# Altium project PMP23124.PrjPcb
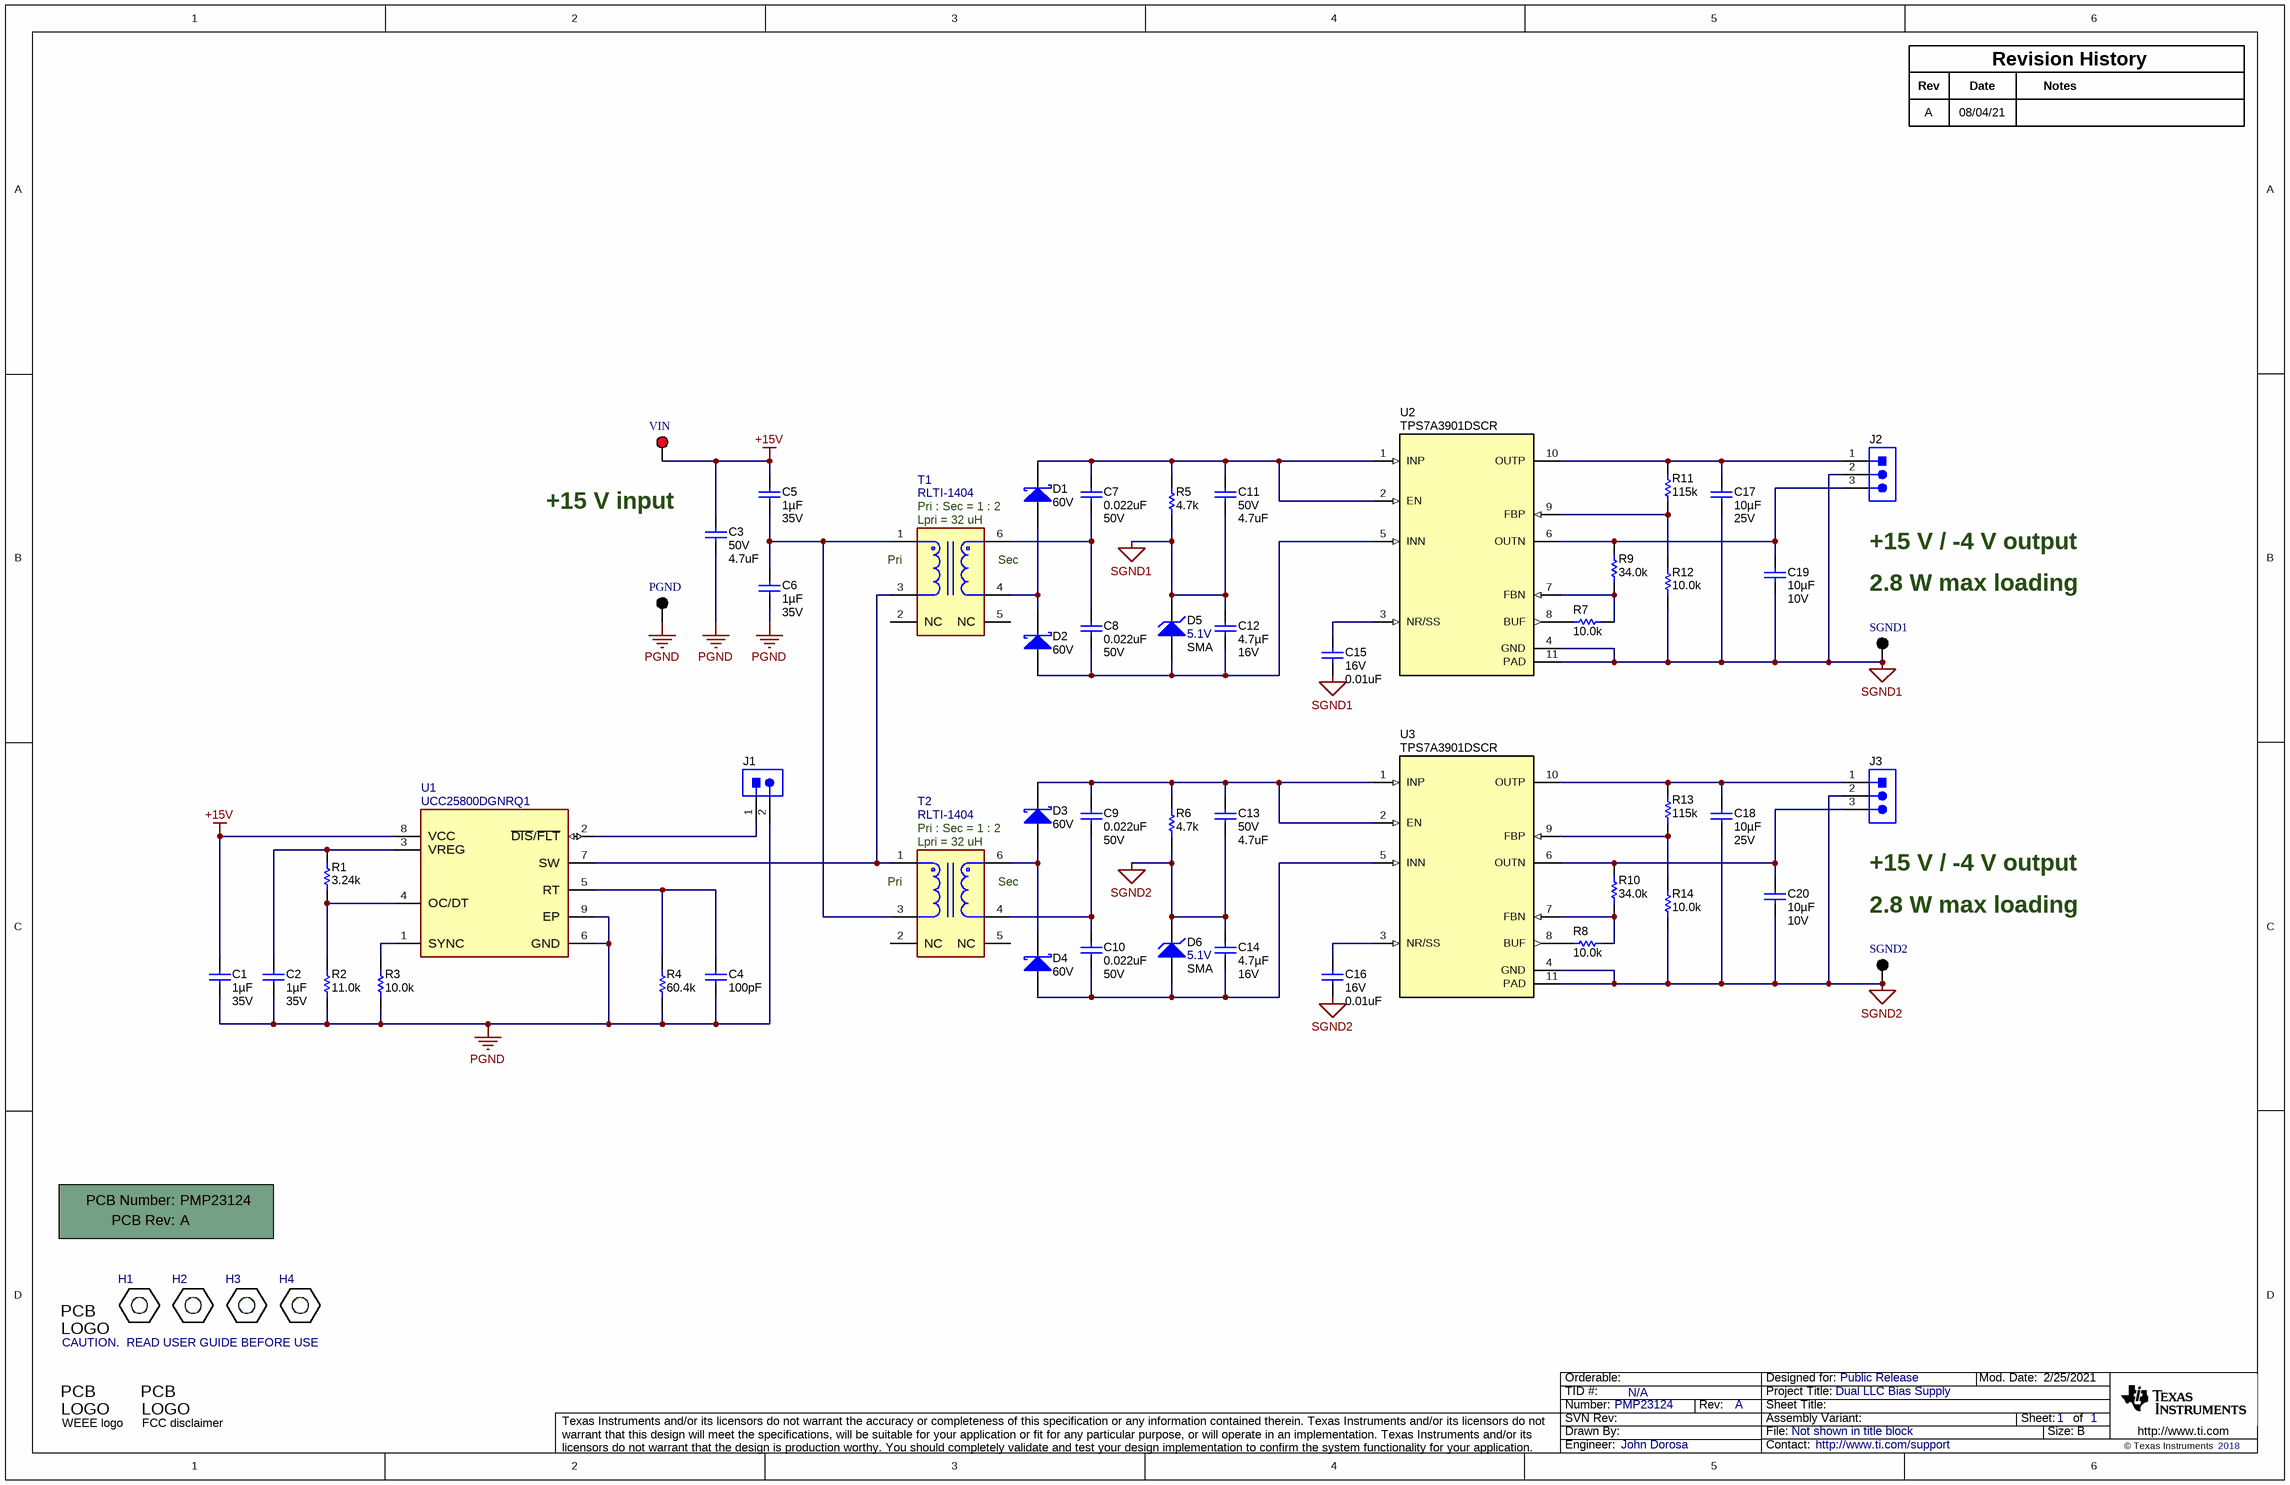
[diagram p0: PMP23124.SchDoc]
TID: N/A; TechSupport: http://www.ti.com/support; SCH_Rev: A; PRJ_Title: Dual LLC Bias Supply; PRJ_Number: PMP23124; PRJ_Engineer: John Dorosa; PRJ_Customer: Public Release; PCB_Rev: A; PCB_Layout: John Dorosa; CopyrightYear: 2018
1 sheet, 60 parts. Net scope: global (net labels, ports and power ports of the same name join across sheets).
Board file: PMP23124.PcbDoc

## Sheet PMP23124.SchDoc
size 431 x 279 mm; Date: Not shown in title block; ApprovedBy: Not shown in title block; CheckedBy: Not shown in title block; Author: Not shown in title block; CompanyName: Not shown in title block; Engineer: Not shown in title block; Organization: Not shown in title block; Address1: Not shown in title block; Address2: Not shown in title block; Address3: Not shown in title block; Address4: Not shown in title block; DocumentNumber: 1; Revision: Use project parameter SCH_Rev; SheetNumber: 1; SheetTotal: 1; PageSetup: Record=PageOptions¦CenterHorizontal=True¦CenterVertical=True¦PrintScale=1.00¦XCorrection=1.00¦YCorrection=1.00¦PrintKind=0¦BorderSize=5000000¦LeftOffset=0¦BottomOffset=0¦Orientation=2¦PaperLength=1000¦PaperWidth=1000¦Scale=100¦PaperSource=15¦PrintQuality=600¦MediaType=1¦DitherType=10¦PaperKind=Letter¦PrintScaleMode=1

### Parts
!PCB1  Printed Circuit Board  (value not drawn)  (mechanical)
C1  Cap_F: 1µF  VDC_V: 35V  [0805_HV]  (hidden comment: GRM219R7YA105KA12D)
C2  Cap_F: 1µF  VDC_V: 35V  [0805_HV]  (hidden comment: GRM219R7YA105KA12D)
C3  VDC_V: 50V  ValueDisplayed: 4.7uF  [1206_180]  (hidden comment: GRM31CR71H475KA12L)
C4  ValueDisplayed: 100pF  [0603]  (hidden comment: GRM1885C1H101JA01D)
C5  Cap_F: 1µF  VDC_V: 35V  [0805_HV]  (hidden comment: GRM219R7YA105KA12D)
C6  Cap_F: 1µF  VDC_V: 35V  [0805_HV]  (hidden comment: GRM219R7YA105KA12D)
C7  value 0.022uF  VDC_V: 50V  [0603]  (hidden comment: GRM188R71H223KA01D)
C8  value 0.022uF  VDC_V: 50V  [0603]  (hidden comment: GRM188R71H223KA01D)
C9  value 0.022uF  VDC_V: 50V  [0603]  (hidden comment: GRM188R71H223KA01D)
C10  value 0.022uF  VDC_V: 50V  [0603]  (hidden comment: GRM188R71H223KA01D)
C11  VDC_V: 50V  ValueDisplayed: 4.7uF  [1206_180L]  (hidden comment: GRM31CR71H475KA12L)
C12  Cap_F: 4.7µF  VDC_V: 16V  [0603]  (hidden comment: GRM188Z71C475KE21D)
C13  VDC_V: 50V  ValueDisplayed: 4.7uF  [1206_180L]  (hidden comment: GRM31CR71H475KA12L)
C14  Cap_F: 4.7µF  VDC_V: 16V  [0603]  (hidden comment: GRM188Z71C475KE21D)
C15  VDC_V: 16V  ValueDisplayed: 0.01uF  [0603]  (hidden comment: GRM188R71C103KA01D)
C16  VDC_V: 16V  ValueDisplayed: 0.01uF  [0603]  (hidden comment: GRM188R71C103KA01D)
C17  Cap_F: 10µF  VDC_V: 25V  [0805L]  (hidden comment: GRM21BZ71E106KE15L)
C18  Cap_F: 10µF  VDC_V: 25V  [0805L]  (hidden comment: GRM21BZ71E106KE15L)
C19  Cap_F: 10µF  VDC_V: 10V  [0603]  (hidden comment: GRM188Z71A106MA73D)
C20  Cap_F: 10µF  VDC_V: 10V  [0603]  (hidden comment: GRM188Z71A106MA73D)
D1  Vr_V: 60V  [SOD-123]  (hidden comment: PMEG6010CEGWJ)
D2  Vr_V: 60V  [SOD-123]  (hidden comment: PMEG6010CEGWJ)
D3  Vr_V: 60V  [SOD-123]  (hidden comment: PMEG6010CEGWJ)
D4  Vr_V: 60V  [SOD-123]  (hidden comment: PMEG6010CEGWJ)
D5  value 5.1V  [SMA]  (hidden comment: SMAZ5V1-13-F)
D6  value 5.1V  [SMA]  (hidden comment: SMAZ5V1-13-F)
H1  4824  [KEYSTONE_4824]  (value not drawn)
H2  4824  [KEYSTONE_4824]  (value not drawn)
H3  4824  [KEYSTONE_4824]  (value not drawn)
H4  4824  [KEYSTONE_4824]  (value not drawn)
J1  22284023  [Molex_0022284023]  (value not drawn)
J2  22284033  [Molex_0022284033]  (value not drawn)
J3  22284033  [Molex_0022284033]  (value not drawn)
Logo1  CAUTION.  READ USER GUIDE BEFORE USE  [IEC_Caution_Small]  (no BOM)
Logo2  WEEE logo  [WEEE_Minimum]  (no BOM)
Logo3  FCC disclaimer  [FCC_disclaimer]  (no BOM)
PGND  5011  [Keystone5011]  (value not drawn)
R1  ValueDisplayed: 3.24k  [0603]  (hidden comment: CRCW06033K24FKEA)
R2  ValueDisplayed: 11.0k  [0603]  (hidden comment: CRCW060311K0FKEA)
R3  ValueDisplayed: 10.0k  [0603]  (hidden comment: CRCW060310K0FKEA)
R4  ValueDisplayed: 60.4k  [0603]  (hidden comment: CRCW060360K4FKEA)
R5  ValueDisplayed: 4.7k  [1210]  (hidden comment: RC1210JR-074K7L)
R6  ValueDisplayed: 4.7k  [1210]  (hidden comment: RC1210JR-074K7L)
R7  ValueDisplayed: 10.0k  [0603]  (hidden comment: CRCW060310K0FKEA)
R8  ValueDisplayed: 10.0k  [0603]  (hidden comment: CRCW060310K0FKEA)
R9  ValueDisplayed: 34.0k  [0603]  (hidden comment: CRCW060334K0FKEA)
R10  ValueDisplayed: 34.0k  [0603]  (hidden comment: CRCW060334K0FKEA)
R11  ValueDisplayed: 115k  [0603]  (hidden comment: CRCW0603115KFKEA)
R12  ValueDisplayed: 10.0k  [0603]  (hidden comment: CRCW060310K0FKEA)
R13  ValueDisplayed: 115k  [0603]  (hidden comment: CRCW0603115KFKEA)
R14  ValueDisplayed: 10.0k  [0603]  (hidden comment: CRCW060310K0FKEA)
SGND1  5011  [Keystone5011]  (value not drawn)
SGND2  5011  [Keystone5011]  (value not drawn)
T1  RLTI-1404  [FP-RLTI-1404_TRANSFORMER_0IN577_0IN37-MFG]
T2  RLTI-1404  [FP-RLTI-1404_TRANSFORMER_0IN577_0IN37-MFG]
U1  UCC25800DGNRQ1  [DGN0008G-MFG]
U2  TPS7A3901DSCR  [DSC0010J]
U3  TPS7A3901DSCR  [DSC0010J]
VIN  5010  [Keystone5010]  (value not drawn)

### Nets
+15V: C1.1 C3.1 C5.1 U1.8(VCC) VIN.1
PGND: C1.2 C2.2 C3.2 C4.2 C6.2 J1.2 PGND.1 R2.1 R3.1 R4.1 U1.6(GND) U1.9(EP)
SGND1: C11.2 C12.1 C15.2 C17.2 C19.2 D5.1(K) J2.2 R5.1 R12.2 SGND1.1 U2.4(GND) U2.11(PAD)
SGND2: C13.2 C14.1 C16.2 C18.2 C20.2 D6.1(K) J3.2 R6.1 R14.2 SGND2.1 U3.4(GND) U3.11(PAD)
NetC2_1: C2.1 R1.2 U1.3(VREG)
NetC4_1: C4.1 R4.2 U1.5(RT)
NetC5_2: C5.2 C6.1 T1.1 T2.3
NetC7_1: C7.1 C8.2 T1.6
NetC7_2: C7.2 C11.1 D1.1(K) R5.2 U2.1(INP) U2.2(EN)
NetC8_1: C8.1 C12.2 D2.2(A) D5.2(A) U2.5(INN)
NetC9_1: C9.1 C10.2 T2.4
NetC9_2: C9.2 C13.1 D3.1(K) R6.2 U3.1(INP) U3.2(EN)
NetC10_1: C10.1 C14.2 D4.2(A) D6.2(A) U3.5(INN)
NetC15_1: C15.1 U2.3(NR/SS)
NetC16_1: C16.1 U3.3(NR/SS)
NetC17_1: C17.1 J2.1 R11.2 U2.10(OUTP)
NetC18_1: C18.1 J3.1 R13.2 U3.10(OUTP)
NetC19_1: C19.1 J2.3 R9.1 U2.6(OUTN)
NetC20_1: C20.1 J3.3 R10.1 U3.6(OUTN)
NetD1_2: D1.2(A) D2.1(K) T1.4
NetD3_2: D3.2(A) D4.1(K) T2.6
NetJ1_1: J1.1 U1.2(~{DIS}/~{FLT})
NetR1_1: R1.1 R2.2 U1.4(OC/DT)
NetR3_2: R3.2 U1.1(SYNC)
NetR7_1: R7.1 R9.2 U2.7(FBN)
NetR7_2: R7.2 U2.8(BUF)
NetR8_1: R8.1 R10.2 U3.7(FBN)
NetR8_2: R8.2 U3.8(BUF)
NetR11_1: R11.1 R12.1 U2.9(FBP)
NetR13_1: R13.1 R14.1 U3.9(FBP)
NetT1_3: T1.3 T2.1 U1.7(SW)

Not connected (* = marked no-connect by the designer): T1 2(NC) 5(NC); T2 2(NC) 5(NC)

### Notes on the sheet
- Rev
- Date
- Notes
- Revision History
- A
- 08/04/21
- +15 V input
- (near T1) Pri
- Pri : Sec = 1 : 2
- (near T1) Lpri = 32 uH
- (near T1) Sec
- (near J2) +15 V / -4 V output
- 2.8 W max loading
- (near T2) Pri
- (near T2) Lpri = 32 uH
- (near T2) Sec
- (near J3) +15 V / -4 V output

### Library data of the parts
!PCB1 = CMP-0003618-2: Manufacturer: Any; PartNumber: PMP23124
C1 C2 C5 C6 = CMP-0085980-1: CAP, CERM, 1 µF, 35 V,+/- 10%, X7R, 0805; Manufacturer: MuRata; AEC Category: Q200; SizeZ_mm: 1.45; U/M: EA; Cap_Case: 0805; Polarized: N; Value: 1uF; TaMin_C: -55°C; TaMax_C: 125°C; SizeArea_mm2: 2.5; SizeX_mm: 2; SizeY_mm: 1.25; SizeAreaWB_mm2: 6.75
C3 C11 C13 = CMP-0008969-2: CAP, CERM, 4.7 uF, 50 V, +/- 10%, X7R, 1206; Manufacturer: MuRata; TaMin_C: -55°C; Polarized: N; SizeAreaWB_mm2: 10.92; Value1: Unknown; U/M: EA; Value: 4.7uF; TaMax_C: 125°C; SizeZ_mm: 1.8; SizeX_mm: 3.2; SizeY_mm: 1.6; Cap_Case: 2220; SizeArea_mm2: 5.12; Cap_F: 4.7µF; AEC Category: Q200
C4 = CMP-0007171-4: CAP, CERM, 100 pF, 50 V, +/- 5%, C0G/NP0, 0603; Manufacturer: MuRata; TaMin_C: -55°C; Polarized: N; SizeAreaWB_mm2: 4.68; Value1: Unknown; U/M: EA; Value: 100pF; TaMax_C: 125°C; SizeZ_mm: 1; SizeX_mm: 1.6; SizeY_mm: 0.8; Value2: 50V; SizeArea_mm2: 1.28; AEC Category: Q200
C7-C10 = CMP-0007444-5: CAP, CERM, 0.022 uF, 50 V, +/- 10%, X7R, 0603; Manufacturer: MuRata; U/M: EA; SizeX_mm: 1.6; Polarized: N; TaMin_C: -55°C; Cap_F: 22nF; SizeZ_mm: 1; AEC Category: Q200; SizeAreaWB_mm2: 4.68; SizeY_mm: 0.8; TaMax_C: 125°C; SizeArea_mm2: 1.28; MFG_Status: TI_Obsolete; Value1: Unknown
C12 C14 = CMP-0064936-4: CAP, CERM, 4.7 uF, 16 V,+/- 10%, X7R, 0603; Manufacturer: MuRata; TaMin_C: -55°C; Polarized: N; SizeAreaWB_mm2: 4.68; Value1: Unknown; U/M: EA; Value: 4.7uF; TaMax_C: 125°C; SizeZ_mm: 1; SizeX_mm: 1.6; SizeY_mm: 0.8; SizeArea_mm2: 1.28; AEC Category: Q200
C15 C16 = CMP-0007377-4: CAP, CERM, 0.01 uF, 16 V, +/- 10%, X7R, 0603; Manufacturer: MuRata; TaMin_C: -55°C; Polarized: N; SizeAreaWB_mm2: 4.68; Value1: Unknown; U/M: EA; Value: 0.01uF; TaMax_C: 125°C; SizeZ_mm: 1; SizeX_mm: 1.6; SizeArea_mm2: 1.28; Cap_F: 10nF; AEC Category: Q200; SizeY_mm: 0.8
C17 C18 = CMP-0008378-2: CAP, CERM, 10 uF, 25 V, +/- 10%, X7R, 0805; Manufacturer: MuRata; TaMin_C: -55°C; Polarized: N; SizeAreaWB_mm2: 6.75; Value1: Unknown; U/M: EA; Value: 10uF; TaMax_C: 125°C; SizeZ_mm: 1.45; SizeX_mm: 2; SizeY_mm: 1.25; Cap_Case: 0805; SizeArea_mm2: 2.5; AEC Category: Q200
C19 C20 = CMP-0007497-5: CAP, CERM, 10 uF, 10 V, +/- 20%, X7R, 0603; Manufacturer: MuRata; TaMin_C: -55°C; Polarized: N; SizeAreaWB_mm2: 4.68; Value1: Unknown; U/M: EA; Value: 10uF; TaMax_C: 125°C; SizeZ_mm: 1; SizeX_mm: 1.6; SizeY_mm: 0.8; SizeArea_mm2: 1.28; AEC Category: Q200
D1-D4 = CMP-0079239-2: Diode, Schottky, 60 V, 1 A, AEC-Q101, SOD-123; Manufacturer: Nexperia; SizeY_mm: 1.7; AEC Qualified: Y; SizeArea_mm2: 6.545; Vf_V: 660mV; Value: 60V; Value1: 1A; AEC Category: Q101; TJmax_C: 150°C; SizeX_mm: 3.85; SizeZ_mm: 1.35; SizeAreaWB_mm2: 13.095; Value2: 0.66V
D5 D6 = CMP-0005529-3: Diode, Zener, 5.1 V, 1 W, SMA; Manufacturer: Diodes Inc.; RJA_CperW: 125; SizeArea_mm2: 16.3228; AEC Category: Q101; SizeX_mm: 5.59; Value1: 1W; SizeZ_mm: 2.87; SizeAreaWB_mm2: 37.3428; SizeY_mm: 2.92
H1-H4 = CMP-0003690-1: Manufacturer: Keystone; CompType: Standoff
J1 = CMP-0055333-1: Header, 2.54mm, 2x1, Tin, TH; Manufacturer: Molex; CNHeader: TRUE; Current_A: 4A; Shrouded: N; Gender: Male; Voltage_V: 250V; Row_Count: 1; Pitch_mm: 2.54; CT: FALSE; Cert_UL: Y
J2 J3 = CMP-0055332-1: Header, 2.54mm, 3x1, Tin, TH; Manufacturer: Molex; CNHeader: TRUE; Current_A: 4A; Shrouded: N; Gender: Male; Voltage_V: 250V; Row_Count: 1; Pitch_mm: 2.54; CT: FALSE; Cert_UL: Y
Logo1 = CMP-0074836-1: IEC 61010-1 Caution Warning; SymbolCreator: a0412235; Lib Reference: IEC_Caution
Logo2 = CMP-0074769-1
Logo3 = CMP-0074847-1: FCC_disclaimer; Library Reference: Logo
PGND SGND1 SGND2 = CMP-0055148-1: Test Point, Multipurpose, Black, TH; Manufacturer: Keystone; CNHeader: FALSE; Green_Lifecycle: Active; Green_REACh: Passed; ContactFinish: Silver; CT: TRUE
R1 = CMP-0022374-4: RES, 3.24 k, 1%, 0.1 W, AEC-Q200 Grade 0, 0603; Manufacturer: Vishay-Dale; Power_W: 100mW; TempCo: 100 ppm/C; Value_Code: 3k24; Value: 3.24k; EIA_Code: E96; SizeX_mm: 1.6; SizeY_mm: 0.8; SizeZ_mm: 1; Value2: 0.1W; SizeArea_mm2: 1.28; AEC Qualified: Y; VDC_V: 75V; AEC Category: Q200; AEC Grade: 0
R2 = CMP-0022016-4: RES, 11.0 k, 1%, 0.1 W, AEC-Q200 Grade 0, 0603; Manufacturer: Vishay-Dale; Power_W: 100mW; TempCo: 100 ppm/C; Value_Code: 11k0; Value: 11.0k; EIA_Code: E96; Res_ohm: 11k; SizeX_mm: 1.6; SizeY_mm: 0.8; SizeZ_mm: 1; Value2: 0.1W; SizeArea_mm2: 1.28; AEC Qualified: Y; VDC_V: 75V; AEC Category: Q200; AEC Grade: 0
R3 R7 R8 R12 R14 = CMP-0021998-4: RES, 10.0 k, 1%, 0.1 W, AEC-Q200 Grade 0, 0603; Manufacturer: Vishay-Dale; Power_W: 100mW; TempCo: 100 ppm/C; Value_Code: 10k0; Value: 10.0k; EIA_Code: E96; Res_ohm: 10k; SizeX_mm: 1.6; SizeY_mm: 0.8; SizeZ_mm: 1; Value2: 0.1W; SizeArea_mm2: 1.28; AEC Qualified: Y; VDC_V: 75V; AEC Category: Q200; AEC Grade: 0
R4 = CMP-0022532-4: RES, 60.4 k, 1%, 0.1 W, AEC-Q200 Grade 0, 0603; Manufacturer: Vishay-Dale; Power_W: 100mW; TempCo: 100 ppm/C; Value_Code: 60k4; Value: 60.4k; EIA_Code: E96; SizeX_mm: 1.6; SizeY_mm: 0.8; SizeZ_mm: 1; Value2: 0.1W; SizeArea_mm2: 1.28; AEC Qualified: Y; VDC_V: 75V; AEC Category: Q200; AEC Grade: 0
R5 R6 = CMP-0083561-1: RES, 4.7 k, 5%, 0.5 W, 1210; Manufacturer: Yageo; Power_W: 500mW; TempCo: 100 ppm/C; SizeAreaWB_mm2: 14.7; Value_Code: 4k70; Value: 4.7k; EIA_Code: E24; SizeX_mm: 3.2; SizeY_mm: 2.5; SizeZ_mm: 1.35; Value2: 0.5W; SizeArea_mm2: 8; AEC Qualified: N; VDC_V: 200V; AEC Category: Q200
R9 R10 = CMP-0022346-4: RES, 34.0 k, 1%, 0.1 W, AEC-Q200 Grade 0, 0603; Manufacturer: Vishay-Dale; Power_W: 100mW; TempCo: 100 ppm/C; Value_Code: 34k0; Value: 34.0k; EIA_Code: E96; Res_ohm: 34k; SizeX_mm: 1.6; SizeY_mm: 0.8; SizeZ_mm: 1; Value2: 0.1W; SizeArea_mm2: 1.28; AEC Qualified: Y; VDC_V: 75V; AEC Category: Q200; AEC Grade: 0
R11 R13 = CMP-0022012-4: RES, 115 k, 1%, 0.1 W, AEC-Q200 Grade 0, 0603; Manufacturer: Vishay-Dale; Power_W: 100mW; TempCo: 100 ppm/C; Value: 115k; EIA_Code: E96; SizeX_mm: 1.6; SizeY_mm: 0.8; SizeZ_mm: 1; Value2: 0.1W; SizeArea_mm2: 1.28; AEC Qualified: Y; VDC_V: 75V; AEC Category: Q200; AEC Grade: 0
T1 T2 = CMP-0092417-1: 3:5 OPEN LOOP LLC FOR PMP22930; Manufacturer: Renco Electronics; SizeZ_mm: 0.404inch; DCR_ohm: 0.18; Ind_H: 45µH; AEC Qualified: No; Cap_F: 2.5pF; Voltage_Isolation_Vrms: 3kV; Rsec1_ohm: 0.31
U1 = CMP-0088494-2: Open Loop LLC Transformer Driver for Isolated Bias Supplies; Manufacturer: Texas Instruments; Min Supply Voltage: 12V; SizeZ_mm: 1.1mm; Number Of Outputs: 1; Standoff Height: 0.05mm; AEC Category: Q200; Max Duty Cycle: 50%; TaMin_C: -40°C; TJmax_C: +150°C; AEC Qualified: No; Switching Frequency: 100-2000kHz; CompType: IC; Max Supply Voltage: 36V; TaMax_C: +125°C; Output Type: Other; Nominal Supply Current: 500uA
U2 U3 = CMP-0013435-7: Dual, 150mA, Wide-Vin, Positive and Negative Low-Dropout (LDO) Voltage Regulator, DSC0010J (WSON-10); Alternate Manufacturer: Texas Instruments; Alternate PartNumber: TPS7A3901DSCT; Rating: Catalog; CompType: IC; SizeAreaWB_mm2: 16.0; SizeY_mm: 3.0; AEC Qualified: N; SizeZ_mm: 0.8; SizeArea_mm2: 9.0; AEC Category: Q200
VIN = CMP-0055147-1: Test Point, Multipurpose, Red, TH; Manufacturer: Keystone; CNHeader: FALSE; Green_Lifecycle: Active; Green_REACh: Passed; ContactFinish: Silver; CT: TRUE

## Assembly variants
001: not fitted H1 H2 H3 H4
